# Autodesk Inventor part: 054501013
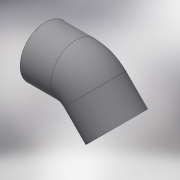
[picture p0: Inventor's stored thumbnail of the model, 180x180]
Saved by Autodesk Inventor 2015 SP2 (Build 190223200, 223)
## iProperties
Created: 2017-10
Part Number: 054501013
Material: Generic
Description: PLASSON THREADED 45° ELBOW HF 1.1/4"
Document SubType Name: Modeling
Designer: KIM
Mass: 43.1922 g
Surface Area: 186.303 cm^2
Volume: 43.1922 cm^3
Density: 1 g/cm^3
Appearance: Default
Author: KIM
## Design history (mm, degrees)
derived "054501.ipt"
feature "Solid1::054501.ipt"
tag "TaggingFeature1"
body "Solid1"
other parameters: "d7" = 0.38952, "d9" = 48, "d13" = 135 deg, "d19" = 45 deg, "d20" = 38.952, "d21" = 22, "d22" = 0, "d28" = 32, "d29" = 38.952, "d30" = 22, "d31" = 0, "d32" = 35.0568, "d33" = 45 deg, "E_" = 48, "lt_" = 22, "G_" = 38.952
